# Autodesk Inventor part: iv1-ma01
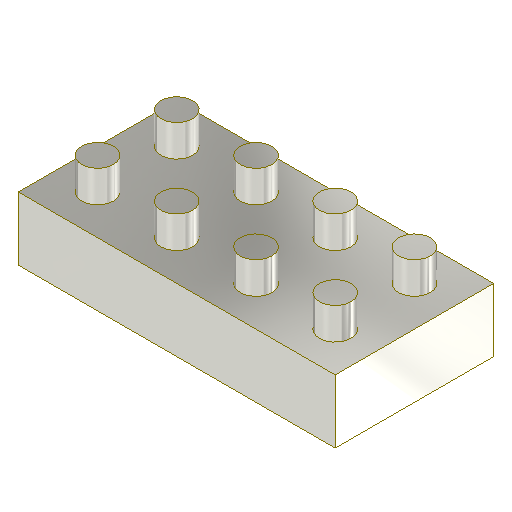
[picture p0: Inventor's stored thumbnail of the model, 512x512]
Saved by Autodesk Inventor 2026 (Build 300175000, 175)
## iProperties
Created: 2004-10
Part Number: iv1-ma01
Document SubType Name: Modeling
Designer: Lars Bertram Pedersen
Manufacturer: Standard
Standards Organization: Custom
Material: ABS Plastic
Density: 1.06 g/cm^3
Appearance: Silver
Mass: 112.66 g
Surface Area: 185.133 cm^2
Volume: 106.283 cm^3
Description: Den lille klods....
Stock Number: 1001
Author: Lars Bertram Pedersen
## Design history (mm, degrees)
sketch "Sketch1"
  geometry: L1 (0, 0)-(100, 0); L2 (100, 0)-(100, 50); L3 (100, 50)-(0, 50); L4 (0, 50)-(0, 0); 1 further point
  constraints: 8 end point, 2 parallel, 1 coincident, 1 horizontal, 1 perpendicular
  dimensions: "d0" = 100 distance of L1.start L1.end; "d1" = 50 distance of L3.end L1.start
extrude "Extrusion1" new body sketch "Sketch1" distance "d2" = 20; taper "d3" = 0 deg
sketch "Sketch2"
  geometry: L1 (0, 0)-(0, 50) reference; L2 (100, 0)-(0, 0) reference; C1 r 5 at (12.5, 12.5); C2 r 5 at (37.5, 12.5); C3 r 5 at (62.5, 12.5); C4 r 5 at (87.5, 12.5); C5 r 5 at (12.5, 37.5); C6 r 5 at (37.5, 37.5); C7 r 5 at (62.5, 37.5); C8 r 5 at (87.5, 37.5)
  constraints: 8 centre point, 1 horizontal, 1 vertical, 14 other
  dimensions: "d4" = 10 diameter of C1; "d5" = 12.5 distance from line of L2 C1.centre; "d6" = 12.5 distance from line of L1 C1.centre; "d9" = 25 distance of C1.centre C2.centre; "d12" = 25 distance of C1.centre C5.centre
extrude "Extrusion2" join sketch "Sketch2" distance "d15" = 10; taper "d16" = 0 deg
body "Solid1"
node "Sketch Rectangular Pattern1" dims "d9" = 25, "d12" = 25
